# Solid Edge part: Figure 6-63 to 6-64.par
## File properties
Author: Ashutosh-CADCIM
Template: Iso Metric Part.par
Last saved by: Ashutosh-CADCIM
Revision: 1
Application: Solid Edge
Accuracy: 0.990
Username: Ashutosh-CADCIM
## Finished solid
Body 1: solid body, 7 faces, 14 edges, 8 vertices.
  Faces by surface: plane 6, cylinder 1
  Edges by curve: line 12, circle 2
Bounding box of the edges (mm): 150.000 x 175.000 x 20.000, from (-75, -80, -10) to (75, 95, 10).
Cylindrical faces by radius (mm): R10 x1
Planar faces by outward normal: +x 1, +y 1, +z 1, -x 1, -y 1, -z 1
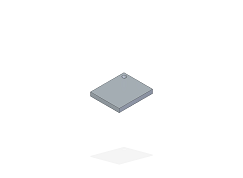
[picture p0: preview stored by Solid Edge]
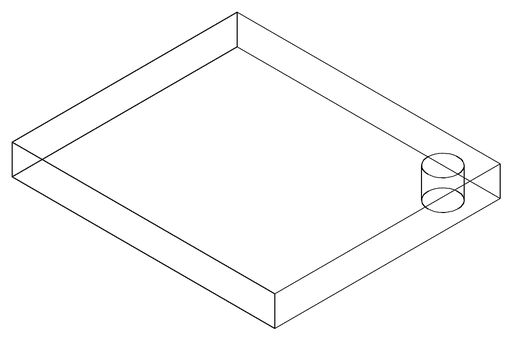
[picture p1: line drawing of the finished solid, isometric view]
